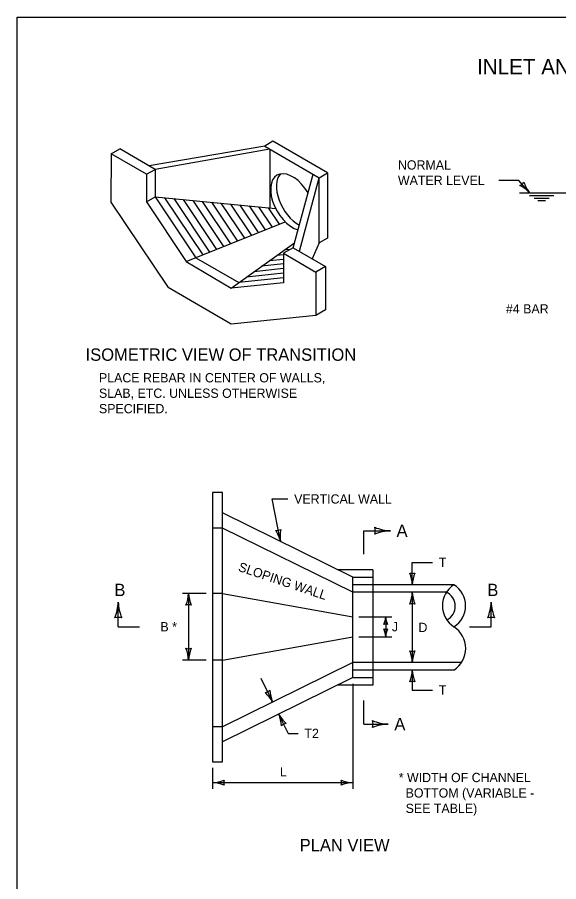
# Model space of a CAD drawing. Extents: x 49991.4 to 50043, y 49987.6 to 50011.4.
# Drawn here: x 49999.38 to 50002.89, y 49993.4 to 49999 of the extents above; entities that cross this region are included whole.
import ezdxf

# ---------------------------------------------------------------- set-up
doc = ezdxf.new("R2010")
doc.units = 0
for name, color, linetype in [('Level 1', 7, 'Continuous'), ('Level 2', 7, 'Continuous'), ('Level 3', 7, 'Continuous'), ('Level 4', 7, 'Continuous'), ('Level 6', 7, 'Continuous')]:
    doc.layers.add(name, color=color, linetype=linetype)

msp = doc.modelspace()

# ---------------------------------------------------------------- linework, layer by layer
at = {"layer": 'Level 1'}
for p, q in [((50001.04, 49998.1956), (50000.9869, 49998.1648)), ((50001.394, 49997.9911), (50001.04, 49998.1956)), ((49999.9925, 49998.1146), (50000.047, 49998.1461)), ((50000.276, 49998.0139), (50000.047, 49998.1461)), ((50000.987, 49998.1648), (50000.238, 49998.0359)), ((50001.0207, 49998.1451), (50000.276, 49998.0139)), ((50000.9869, 49998.1648), (50001.3395, 49997.9596)), ((50001.0207, 49998.1451), (50001.0195, 49997.7642)), ((49999.9925, 49998.1146), (49999.9904, 49997.8017)), ((50000.2215, 49997.9824), (49999.9925, 49998.1146)), ((50000.2215, 49997.9824), (50000.276, 49998.0139)), ((50000.2215, 49997.9824), (50000.2215, 49997.8046)), ((50000.276, 49998.0139), (50000.276, 49997.8361)), ((50001.172, 49997.5066), (50001.2998, 49997.9827)), ((50001.3395, 49997.9596), (50001.394, 49997.9911)), ((50001.394, 49997.9911), (50001.394, 49997.5687)), ((50001.2118, 49997.4834), (50001.3395, 49997.9596)), ((50001.3395, 49997.5372), (50001.3395, 49997.9596)), ((50002.638, 49997.8625), (50002.9684, 49997.8625)), ((49999.9904, 49997.8017), (50000.3604, 49997.248)), ((50000.2215, 49997.8046), (50000.276, 49997.8361)), ((50000.2215, 49997.8046), (50000.4785, 49997.4164)), ((50000.276, 49997.8361), (50000.5399, 49997.4411)), ((50000.276, 49997.8361), (50001.0575, 49997.7605)), ((50000.3371, 49997.8302), (50000.5849, 49997.4592)), ((50000.3981, 49997.8243), (50000.6299, 49997.4773)), ((50000.4592, 49997.8184), (50000.6749, 49997.4954)), ((50000.5202, 49997.8125), (50000.72, 49997.5135)), ((50000.5813, 49997.8066), (50000.765, 49997.5316)), ((50002.7032, 49997.8436), (50002.8611, 49997.8436)), ((50002.7324, 49997.8265), (50002.8294, 49997.8265)), ((50002.7573, 49997.8123), (50002.8068, 49997.8123)), ((50000.6424, 49997.8007), (50000.81, 49997.5497)), ((50000.7034, 49997.7948), (50000.8551, 49997.5678)), ((50000.7645, 49997.7889), (50000.9001, 49997.5859)), ((50000.8255, 49997.783), (50000.9451, 49997.604)), ((50000.8866, 49997.7771), (50000.9901, 49997.622)), ((50000.9476, 49997.7712), (50001.0352, 49997.6401)), ((50001.0087, 49997.7652), (50001.0802, 49997.6582)), ((50000.4785, 49997.4164), (50001.1196, 49997.6741)), ((50000.7685, 49997.2452), (50001.1804, 49997.5378)), ((50001.1779, 49997.5285), (50001.1653, 49997.5271)), ((50001.3395, 49997.5372), (50001.2947, 49997.4351)), ((50001.394, 49997.5687), (50001.3395, 49997.5372)), ((50001.172, 49997.5066), (50001.109, 49997.4702)), ((50001.109, 49997.4702), (50001.109, 49997.2791)), ((50001.109, 49997.4702), (50001.3172, 49997.3483)), ((50001.1533, 49997.4958), (50001.1157, 49997.4919)), ((50001.172, 49997.5066), (50001.3808, 49997.3849)), ((50000.4785, 49997.4164), (50000.7685, 49997.2452)), ((50000.5399, 49997.4411), (50000.8181, 49997.2805)), ((50001.109, 49997.4311), (50001.0165, 49997.4214)), ((50001.109, 49997.4611), (50001.0661, 49997.4567)), ((50001.109, 49997.371), (50000.9173, 49997.3509)), ((50001.109, 49997.401), (50000.9669, 49997.3862)), ((50001.3808, 49997.3849), (50001.3172, 49997.3483)), ((50001.3808, 49997.3849), (50001.3808, 49997.1042)), ((50001.109, 49997.3108), (50000.8181, 49997.2805)), ((50001.109, 49997.3409), (50000.8677, 49997.3157)), ((50001.3172, 49997.3483), (50001.3172, 49997.0674)), ((50000.7692, 49997.012), (50000.3604, 49997.248)), ((50001.109, 49997.2791), (50000.7685, 49997.2452)), ((50001.3808, 49997.1042), (50001.3172, 49997.0674)), ((50001.3172, 49997.0674), (50000.7692, 49997.012)), ((50000.7127, 49995.9197), (50000.6477, 49995.9197)), ((50000.6477, 49995.9197), (50000.6477, 49994.1757)), ((50000.7127, 49994.1757), (50000.7127, 49995.9197)), ((50001.5577, 49995.3715), (50000.7127, 49995.7897)), ((50000.7127, 49995.6898), (50000.6477, 49995.6898)), ((50001.5577, 49995.274), (50000.7127, 49995.6898)), ((50001.6877, 49995.4203), (50001.4591, 49995.4203)), ((50001.6877, 49995.4203), (50001.6877, 49994.6728)), ((50001.5577, 49994.7215), (50001.5577, 49995.3715)), ((50002.2129, 49995.3228), (50001.5577, 49995.3228)), ((50000.7127, 49995.2668), (50000.6477, 49995.2668)), ((50000.7127, 49995.2668), (50001.5577, 49995.1159)), ((50000.7127, 49994.835), (50001.5577, 49994.9859)), ((50000.7127, 49994.835), (50000.6477, 49994.835)), ((50001.5577, 49994.819), (50000.7127, 49994.4032)), ((50001.5577, 49994.7215), (50000.7127, 49994.3057)), ((50002.2129, 49994.7703), (50001.5577, 49994.7703)), ((50001.6877, 49994.6728), (50001.4587, 49994.6728)), ((50000.7127, 49994.4032), (50000.6477, 49994.4032)), ((50000.6477, 49994.1757), (50000.7127, 49994.1757))]:
    msp.add_line(p, q, dxfattribs=at)
msp.add_lwpolyline([(49999.3835, 49998.9992), (50016.7501, 49998.9992), (50016.7501, 49987.7988), (49999.3835, 49987.7988)], close=True, dxfattribs=at)
for centre, radius, start, end in [((50002.2989, 49995.1868), 0.1609, 122.3335, 237.6665), ((50002.1287, 49995.1868), 0.1599, 301.772, 58.228), ((50002.1228, 49995.1842), 0.0988, 296.2298, 65.513), ((50002.1227, 49994.9106), 0.1667, 302.7325, 57.2885)]:
    msp.add_arc(centre, radius, start, end, dxfattribs=at)
for centre, start_param, end_param in [((50001.1679, 49997.8013), 4.726836, 8.88612), ((50001.2051, 49997.8211), 0.161802, 2.399384)]:
    msp.add_ellipse(centre, major_axis=(-0.101, 0.1749), ratio=0.57735, start_param=start_param, end_param=end_param, dxfattribs=at)
at = {"layer": 'Level 3'}
for p, q in [((50002.6342, 49997.9428), (50002.5043, 49997.9428)), ((50002.703, 49997.8625), (50002.6342, 49997.9428)), ((50001.0342, 49995.8787), (50001.1374, 49995.8787)), ((50001.0886, 49995.6037), (50001.0342, 49995.8787)), ((50001.9432, 49995.3228), (50001.9432, 49995.468)), ((50001.9432, 49995.468), (50002.075, 49995.468)), ((50000.6077, 49995.2668), (50000.4535, 49995.2668)), ((50000.4935, 49995.2668), (50000.4935, 49994.835)), ((50001.9432, 49995.274), (50001.9432, 49994.819)), ((50001.5977, 49995.1159), (50001.8106, 49995.1159)), ((50001.7706, 49995.1159), (50001.7706, 49994.9859)), ((50001.5977, 49994.9859), (50001.8106, 49994.9859)), ((50000.6077, 49994.835), (50000.4535, 49994.835)), ((50001.9432, 49994.7703), (50001.9432, 49994.6409)), ((50000.9609, 49994.7187), (50001.0381, 49994.5633)), ((50001.5577, 49994.6815), (50001.5577, 49994.001)), ((50001.9432, 49994.6409), (50002.075, 49994.6409)), ((50001.077, 49994.485), (50001.1392, 49994.3599)), ((50001.1392, 49994.3599), (50001.2042, 49994.3599)), ((50000.6477, 49994.1357), (50000.6477, 49994.001)), ((50000.6477, 49994.041), (50001.5577, 49994.041))]:
    msp.add_line(p, q, dxfattribs=at)
for centre, radius, start, end in [((50002.6196, 49997.9599), 0.0548, 292.7196, 328.442), ((50002.8873, 49998.0052), 0.233, 198.5036, 217.7535), ((50002.5403, 49997.7111), 0.2223, 42.9413, 63.1248), ((50001.0637, 49995.7295), 0.0548, 263.3245, 299.0469), ((50000.8625, 49995.5473), 0.233, 14.013, 33.2629), ((50001.3083, 49995.6378), 0.2223, 168.6417, 188.8252), ((50001.8133, 49995.969), 0.2964, 247.456, 267.6395), ((50001.6301, 49995.6728), 0.073, 342.1388, 17.8612), ((50001.8164, 49995.3625), 0.3107, 92.8273, 112.0772), ((50001.9432, 49995.451), 0.0548, 252.1388, 287.8612), ((50001.7105, 49995.3113), 0.233, 2.8273, 22.0772), ((50002.1653, 49995.3137), 0.2223, 157.456, 177.6395), ((50000.2714, 49995.276), 0.2223, 337.456, 357.6395), ((50000.7262, 49995.2783), 0.233, 182.8273, 202.0772), ((50001.7211, 49995.2832), 0.2223, 337.456, 357.6395), ((50002.1759, 49995.2855), 0.233, 182.8273, 202.0772), ((49999.7415, 49995.2215), 0.2964, 337.456, 357.6395), ((50000.348, 49995.2246), 0.3107, 182.8273, 202.0772), ((50000.4935, 49995.1386), 0.0548, 72.1388, 107.8612), ((50001.9432, 49995.1458), 0.0548, 72.1388, 107.8612), ((50002.1579, 49995.2215), 0.2964, 337.456, 357.6395), ((50002.7644, 49995.2246), 0.3107, 182.8273, 202.0772), ((50001.6225, 49995.122), 0.1482, 337.456, 357.6395), ((50001.9257, 49995.1236), 0.1553, 182.8273, 202.0772), ((50000.0377, 49995.0384), 0.073, 72.1388, 107.8612), ((50001.7706, 49995.0304), 0.0365, 72.1388, 107.8612), ((50002.4541, 49995.0384), 0.073, 72.1388, 107.8612), ((50001.7706, 49995.0714), 0.0365, 252.1388, 287.8612), ((50001.6155, 49994.9783), 0.1553, 2.8273, 22.0772), ((50001.9187, 49994.9798), 0.1482, 157.456, 177.6395), ((50000.4935, 49994.9632), 0.0548, 252.1388, 287.8612), ((50000.2608, 49994.8235), 0.233, 2.8273, 22.0772), ((50000.7156, 49994.8259), 0.2223, 157.456, 177.6395), ((50001.9432, 49994.9472), 0.0548, 252.1388, 287.8612), ((50001.7105, 49994.8075), 0.233, 2.8273, 22.0772), ((50002.1653, 49994.8099), 0.2223, 157.456, 177.6395), ((50001.7211, 49994.7795), 0.2223, 337.456, 357.6395), ((50002.1759, 49994.7818), 0.233, 182.8273, 202.0772), ((50001.9432, 49994.6421), 0.0548, 72.1388, 107.8612), ((50000.981, 49994.6782), 0.0548, 278.5638, 314.2861), ((50000.8348, 49994.4495), 0.233, 29.2523, 48.5021), ((50001.2411, 49994.654), 0.2223, 183.881, 204.0645), ((50000.874, 49994.3943), 0.2223, 3.8914, 24.0749), ((50001.2803, 49994.5989), 0.233, 209.2627, 228.5126), ((50001.7991, 49994.7165), 0.2964, 247.456, 267.6395), ((50001.6159, 49994.4203), 0.073, 342.1388, 17.8612), ((50001.1341, 49994.3702), 0.0548, 98.5742, 134.2966), ((50001.8022, 49994.11), 0.3107, 92.8273, 112.0772), ((50000.6362, 49994.2737), 0.233, 272.8273, 292.0772), ((50000.7759, 49994.041), 0.0548, 162.1388, 197.8612), ((50001.5669, 49994.2632), 0.2223, 247.456, 267.6395), ((50001.4295, 49994.041), 0.0548, 342.1388, 17.8612), ((50000.6385, 49993.8189), 0.2223, 67.456, 87.6395), ((50001.5692, 49993.8083), 0.233, 92.8273, 112.0772)]:
    msp.add_arc(centre, radius, start, end, dxfattribs=at)
at = {"layer": 'Level 4'}
for p, q in [((50001.5577, 49995.3715), (50001.6877, 49995.3715)), ((50002.1637, 49995.274), (50001.5577, 49995.274)), ((50002.2621, 49994.819), (50001.5577, 49994.819)), ((50001.5577, 49994.7215), (50001.6877, 49994.7215))]:
    msp.add_line(p, q, dxfattribs=at)
at = {"layer": 'Level 6'}
for p, q in [((50001.6296, 49995.6728), (50001.8011, 49995.6728)), ((50001.6296, 49995.5203), (50001.6296, 49995.6728)), ((50000.0377, 49995.0509), (50000.0377, 49995.2093)), ((50002.4541, 49995.0509), (50002.4541, 49995.2093)), ((50000.0377, 49995.0509), (50000.1749, 49995.0509)), ((50002.3129, 49995.0509), (50002.4541, 49995.0509)), ((50001.6296, 49994.4203), (50001.6296, 49994.5728)), ((50001.6296, 49994.4203), (50001.7869, 49994.4203))]:
    msp.add_line(p, q, dxfattribs=at)

# ---------------------------------------------------------------- texts
at = {"layer": 'Level 2'}
for s, height, p in [('INLET AND OUTLET TRANSITION', 0.1, (50002.3625, 49998.6287)), ('NORMAL', 0.06, (50001.8501, 49998.0128)), ('WATER LEVEL', 0.06, (50001.8501, 49997.9128)), ('#4 BAR', 0.06, (50002.5499, 49997.0802)), ('ISOMETRIC VIEW OF TRANSITION', 0.08, (49999.8263, 49996.7738)), ('PLACE REBAR IN CENTER OF WALLS,', 0.06, (49999.9127, 49996.6338)), ('SLAB, ETC. UNLESS OTHERWISE', 0.06, (49999.9127, 49996.5338)), ('SPECIFIED.', 0.06, (49999.9127, 49996.4338)), ('VERTICAL WALL', 0.06, (50001.1774, 49995.8487)), ('A', 0.08, (50001.8411, 49995.6328)), ('T', 0.06, (50002.115, 49995.438)), ('B', 0.08, (50000.0129, 49995.2493)), ('B', 0.08, (50002.4293, 49995.2493)), ('B *', 0.06, (50000.311, 49995.0209)), ('J', 0.06, (50001.8106, 49995.0209)), ('D', 0.06, (50001.9832, 49995.0165)), ('T', 0.06, (50002.115, 49994.6109)), ('A', 0.08, (50001.8269, 49994.3803)), ('T2', 0.06, (50001.2442, 49994.3299)), ('L', 0.06, (50001.0857, 49994.081)), ('* WIDTH OF CHANNEL', 0.06, (50001.8554, 49994.0441)), ('  BOTTOM (VARIABLE -', 0.06, (50001.8554, 49993.9441)), ('  SEE TABLE)', 0.06, (50001.8554, 49993.8441)), ('PLAN VIEW', 0.08, (50001.2135, 49993.5962))]:
    msp.add_text(s, height=height, dxfattribs=at).set_placement(p)
msp.add_text('SLOPING WALL', height=0.06, rotation=341.4654, dxfattribs=at).set_placement((50000.8108, 49995.4137))

doc.saveas('drawing.dxf')
